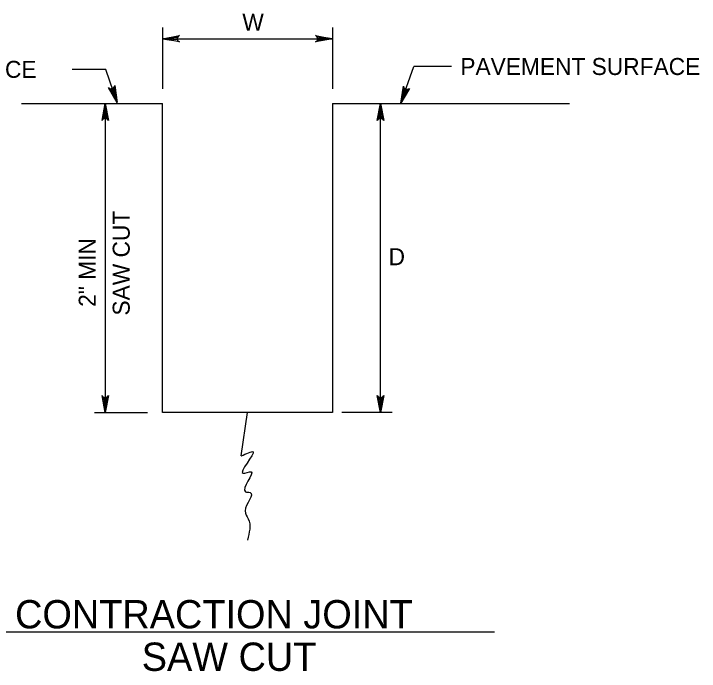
# Model space of a CAD drawing. Extents: x 1.68 to 8.95, y -3.21 to 6.76.
# Drawn here: x 5.56 to 7.98, y 4.435 to 6.756 of the extents above; entities that cross this region are included whole.
import ezdxf

# ---------------------------------------------------------------- set-up
doc = ezdxf.new("R2010")
doc.units = 0
for name, color, linetype in [('DETL-DIMS', 7, 'Continuous'), ('DETL-LINE', 7, 'Continuous'), ('DETL-NOTE', 7, 'Continuous'), ('DETL-TITL', 7, 'Continuous')]:
    doc.layers.add(name, color=color, linetype=linetype)

msp = doc.modelspace()

# ---------------------------------------------------------------- linework, layer by layer
at = {"layer": 'DETL-DIMS'}
for p, q in [((6.085, 6.7077), (6.085, 6.4907)), ((6.685, 6.7077), (6.685, 6.4907)), ((6.085, 6.6679), (6.685, 6.6679)), ((5.8857, 6.56), (5.7662, 6.56)), ((5.9248, 6.4426), (5.8857, 6.56)), ((6.9265, 6.4401), (6.973, 6.5701)), ((7.1058, 6.5701), (6.973, 6.5701)), ((5.8833, 6.4393), (5.8833, 5.3482)), ((6.855, 5.3482), (6.855, 6.4393)), ((5.8448, 5.3482), (6.0328, 5.3482)), ((6.8961, 5.3482), (6.7179, 5.3482))]:
    msp.add_line(p, q, dxfattribs=at)
for points in [[(6.085, 6.6679), (6.1449, 6.6791), (6.1403, 6.6759), (6.1379, 6.6719), (6.1372, 6.6679), (6.1379, 6.6639), (6.1403, 6.6598), (6.1449, 6.6566), (6.085, 6.6679), (6.1403, 6.6598), (6.1379, 6.6639), (6.085, 6.6679), (6.1372, 6.6679), (6.1379, 6.6719), (6.085, 6.6679), (6.1403, 6.6759)], [(6.085, 6.6679), (6.1449, 6.6791), (6.1403, 6.6759), (6.1379, 6.6719), (6.1372, 6.6679), (6.1379, 6.6639), (6.1403, 6.6598), (6.1449, 6.6566), (6.085, 6.6679), (6.1403, 6.6598), (6.1379, 6.6639), (6.085, 6.6679), (6.1372, 6.6679), (6.1379, 6.6719), (6.085, 6.6679), (6.1403, 6.6759)], [(6.685, 6.6679), (6.6251, 6.6566), (6.6297, 6.6598), (6.6321, 6.6639), (6.6328, 6.6679), (6.6321, 6.6719), (6.6297, 6.6759), (6.6251, 6.6791), (6.685, 6.6679), (6.6297, 6.6759), (6.6321, 6.6719), (6.685, 6.6679), (6.6328, 6.6679), (6.6321, 6.6639), (6.685, 6.6679), (6.6297, 6.6598)], [(5.9248, 6.4426), (5.8952, 6.4959), (5.8997, 6.4925), (5.9043, 6.4915), (5.9083, 6.4921), (5.9119, 6.4941), (5.915, 6.4976), (5.9166, 6.503), (5.9248, 6.4426), (5.915, 6.4976), (5.9119, 6.4941), (5.9248, 6.4426), (5.9083, 6.4921), (5.9043, 6.4915), (5.9248, 6.4426), (5.8997, 6.4925)], [(6.9265, 6.4401), (6.9361, 6.5003), (6.9376, 6.4949), (6.9405, 6.4913), (6.9441, 6.4893), (6.9481, 6.4886), (6.9527, 6.4895), (6.9573, 6.4927), (6.9265, 6.4401), (6.9527, 6.4895), (6.9481, 6.4886), (6.9265, 6.4401), (6.9441, 6.4893), (6.9405, 6.4913), (6.9265, 6.4401), (6.9376, 6.4949)], [(5.8833, 6.4393), (5.8945, 6.3794), (5.8913, 6.384), (5.8873, 6.3864), (5.8833, 6.387), (5.8793, 6.3864), (5.8752, 6.384), (5.872, 6.3794), (5.8833, 6.4393), (5.8752, 6.384), (5.8793, 6.3864), (5.8833, 6.4393), (5.8833, 6.387), (5.8873, 6.3864), (5.8833, 6.4393), (5.8913, 6.384)], [(5.8833, 6.4393), (5.8945, 6.3794), (5.8913, 6.384), (5.8873, 6.3864), (5.8833, 6.387), (5.8793, 6.3864), (5.8752, 6.384), (5.872, 6.3794), (5.8833, 6.4393), (5.8752, 6.384), (5.8793, 6.3864), (5.8833, 6.4393), (5.8833, 6.387), (5.8873, 6.3864), (5.8833, 6.4393), (5.8913, 6.384)], [(6.855, 6.4393), (6.8662, 6.3794), (6.863, 6.384), (6.859, 6.3864), (6.855, 6.387), (6.8509, 6.3864), (6.8469, 6.384), (6.8437, 6.3794), (6.855, 6.4393), (6.8469, 6.384), (6.8509, 6.3864), (6.855, 6.4393), (6.855, 6.387), (6.859, 6.3864), (6.855, 6.4393), (6.863, 6.384)], [(5.8833, 5.3482), (5.872, 5.4082), (5.8752, 5.4035), (5.8793, 5.4012), (5.8833, 5.4005), (5.8873, 5.4012), (5.8913, 5.4035), (5.8945, 5.4082), (5.8833, 5.3482), (5.8913, 5.4035), (5.8873, 5.4012), (5.8833, 5.3482), (5.8833, 5.4005), (5.8793, 5.4012), (5.8833, 5.3482), (5.8752, 5.4035)], [(6.855, 5.3482), (6.8437, 5.4082), (6.8469, 5.4035), (6.8509, 5.4012), (6.855, 5.4005), (6.859, 5.4012), (6.863, 5.4035), (6.8662, 5.4082), (6.855, 5.3482), (6.863, 5.4035), (6.859, 5.4012), (6.855, 5.3482), (6.855, 5.4005), (6.8509, 5.4012), (6.855, 5.3482), (6.8469, 5.4035)]]:
    msp.add_lwpolyline(points, dxfattribs=at)
at = {"layer": 'DETL-LINE'}
for p, q in [((5.5881, 6.4393), (6.085, 6.4393)), ((6.085, 5.3482), (6.085, 6.4393)), ((6.685, 6.4393), (6.685, 5.3482)), ((6.685, 6.4393), (7.5218, 6.4393)), ((6.685, 5.3482), (6.085, 5.3482)), ((6.363, 5.1955), (6.385, 5.3482))]:
    msp.add_line(p, q, dxfattribs=at)
msp.add_spline([(6.363, 5.1955), (6.3646, 5.1961), (6.4057, 5.2103), (6.3697, 5.134), (6.3985, 5.1397), (6.378, 5.0691), (6.3944, 5.0663), (6.3769, 5.0013), (6.3882, 4.9731), (6.385, 4.8982)], degree=3, dxfattribs=at)
at = {"layer": 'DETL-NOTE'}
msp.add_line((5.5303, 4.574), (7.257, 4.574), dxfattribs=at)

# ---------------------------------------------------------------- texts
for s, p in [('W', (6.3671, 6.6964)), ('PAVEMENT SURFACE', (4.7936, 6.53)), ('PAVEMENT SURFACE', (7.1367, 6.5401)), ('D', (6.8835, 5.8686))]:
    msp.add_text(s, height=0.06, dxfattribs=at).set_placement(p)
for s, p in [('SAW CUT', (5.9695, 5.6909)), ('2" MIN', (5.8495, 5.7217))]:
    msp.add_text(s, height=0.06, rotation=90, dxfattribs=at).set_placement(p)
at = {"layer": 'DETL-TITL'}
for s, p in [('CONTRACTION JOINT', (5.5648, 4.5865)), ('SAW CUT', (6.012, 4.4365))]:
    msp.add_text(s, height=0.1, dxfattribs=at).set_placement(p)

doc.saveas('drawing.dxf')
